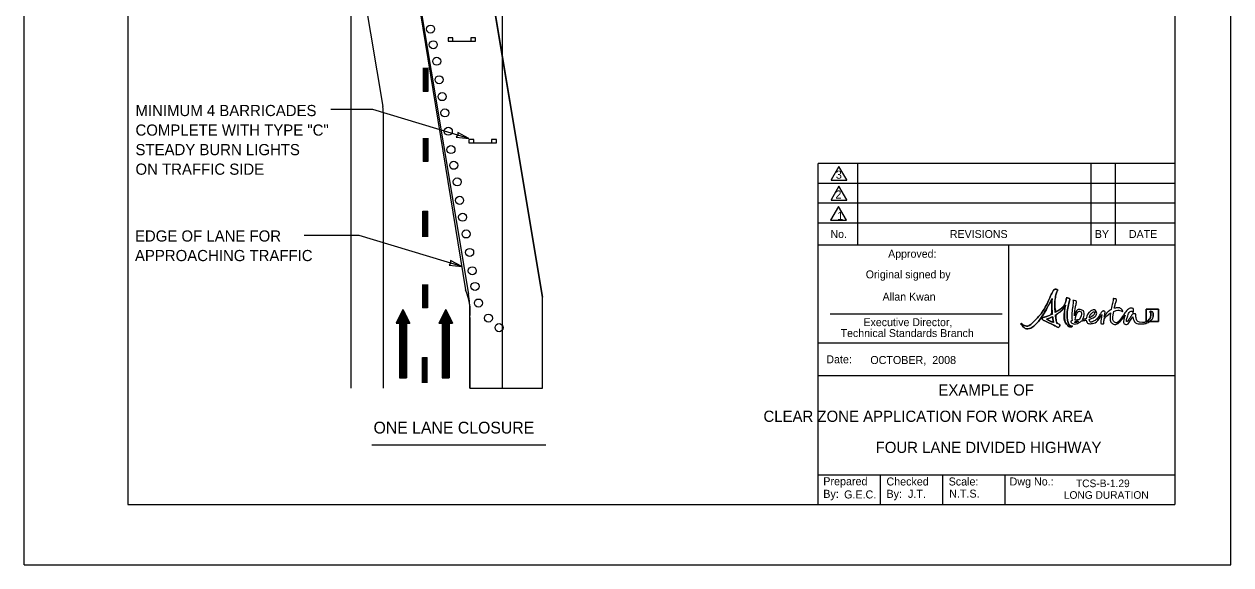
# Model space of a CAD drawing. Extents: x 3033 to 3249, y -403 to -124.
# Drawn here: x 3033.2 to 3249.2, y -402.6 to -305.8 of the extents above; entities that cross this region are included whole.
import ezdxf

# ---------------------------------------------------------------- set-up
doc = ezdxf.new("R2010")
doc.units = 0
for name, color, linetype in [('Level 1', 7, 'Continuous'), ('Level 10', 7, 'Continuous'), ('Level 17', 7, 'Continuous'), ('Level 22', 7, 'Continuous'), ('Level 36', 7, 'Continuous'), ('Level 44', 7, 'Continuous'), ('Level 5', 7, 'Continuous'), ('Level 53', 7, 'Continuous'), ('Level 60', 7, 'Continuous'), ('Level 7', 7, 'Continuous')]:
    doc.layers.add(name, color=color, linetype=linetype)

# ---------------------------------------------------------------- blocks, each defined once
blk = doc.blocks.new('arrow')
at = {"layer": 'Level 60'}
blk.add_lwpolyline([(0.6, 0.12), (0, 0), (0.6, -0.12), (0.56, 0)], close=True, dxfattribs=at)

msp = doc.modelspace()

# ---------------------------------------------------------------- linework, layer by layer
at = {"layer": 'Level 1'}
for p, q in [((3239.21, -334.32), (3175.36, -334.32)), ((3239.21, -337.87), (3175.36, -337.87)), ((3239.21, -341.41), (3175.36, -341.41)), ((3175.37, -391.78), (3175.37, -345.31)), ((3175.37, -345.31), (3239.21, -345.31)), ((3209.42, -345.31), (3209.42, -368.72)), ((3175.37, -362.87), (3209.42, -362.87)), ((3175.37, -368.72), (3239.21, -368.72)), ((3175.37, -386.46), (3239.21, -386.46)), ((3186.5, -391.78), (3186.5, -386.46)), ((3197.63, -391.78), (3197.63, -386.46)), ((3208.76, -386.46), (3208.76, -391.78))]:
    msp.add_line(p, q, dxfattribs=at)
msp.add_lwpolyline([(3178.99, -338.43), (3177.57, -340.9), (3180.41, -340.9)], close=True, dxfattribs=at)
at = {"layer": 'Level 10'}
for p, q in [((3118.83, -370.96), (3118.83, -242.11)), ((3091.73, -370.96), (3091.73, -261.76)), ((3101.51, -286.84), (3112.75, -354.13)), ((3092.01, -288.27), (3097.4, -320.57)), ((3101.92, -289.97), (3112.2, -353.34)), ((3097.54, -370.96), (3097.54, -322.22)), ((3101.02, -356.86), (3099.8, -359.31)), ((3100.26, -358.39), (3100.26, -359.31)), ((3100.41, -358.08), (3100.41, -369.13)), ((3100.56, -357.78), (3100.56, -369.13)), ((3100.71, -357.47), (3100.71, -369.13)), ((3100.87, -357.16), (3100.87, -369.13)), ((3101.02, -356.86), (3101.02, -369.13)), ((3101.02, -356.86), (3102.25, -359.31)), ((3101.18, -357.16), (3101.18, -369.13)), ((3101.33, -357.47), (3101.33, -369.13)), ((3101.48, -357.78), (3101.48, -369.13)), ((3101.64, -358.08), (3101.64, -369.13)), ((3101.79, -358.39), (3101.79, -359.31)), ((3108.68, -356.86), (3107.46, -359.31)), ((3107.92, -358.39), (3107.92, -359.31)), ((3108.07, -358.08), (3108.07, -369.13)), ((3108.22, -357.78), (3108.22, -369.13)), ((3108.37, -357.47), (3108.37, -369.13)), ((3108.53, -357.16), (3108.53, -369.13)), ((3108.68, -356.86), (3108.68, -369.13)), ((3108.68, -356.86), (3109.91, -359.31)), ((3108.84, -357.16), (3108.84, -369.13)), ((3108.99, -357.47), (3108.99, -369.13)), ((3109.14, -357.78), (3109.14, -369.13)), ((3109.3, -358.08), (3109.3, -369.13)), ((3109.45, -358.39), (3109.45, -359.31)), ((3113.02, -370.96), (3113.02, -357.42)), ((3099.8, -359.31), (3100.41, -359.31)), ((3099.95, -359), (3099.95, -359.31)), ((3100.1, -358.7), (3100.1, -359.31)), ((3100.41, -359.31), (3100.41, -369.13)), ((3101.64, -359.31), (3101.64, -369.13)), ((3101.64, -359.31), (3102.25, -359.31)), ((3101.94, -358.7), (3101.94, -359.31)), ((3102.1, -359), (3102.1, -359.31)), ((3107.46, -359.31), (3108.07, -359.31)), ((3107.61, -359), (3107.61, -359.31)), ((3107.76, -358.7), (3107.76, -359.31)), ((3108.07, -359.31), (3108.07, -369.13)), ((3109.3, -359.31), (3109.3, -369.13)), ((3109.3, -359.31), (3109.91, -359.31)), ((3109.6, -358.7), (3109.6, -359.31)), ((3109.76, -359), (3109.76, -359.31)), ((3100.41, -369.13), (3101.64, -369.13)), ((3108.07, -369.13), (3109.3, -369.13))]:
    msp.add_line(p, q, dxfattribs=at)
msp.add_lwpolyline([(3113.02, -358.31), (3113.02, -370.96), (3126.02, -370.96), (3126.02, -354.69), (3114.37, -284.95), (3114.35, -242.11), (3101.45, -242.09), (3101.37, -285.85), (3101.52, -287.39)], dxfattribs=at)
for centre in [(3105.96, -306.68), (3106.45, -309.49), (3107.07, -312.45), (3107.5, -315.75), (3108.04, -318.78), (3108.52, -321.68), (3109.14, -324.97), (3109.62, -328.26), (3110.11, -331.07), (3110.73, -334.03), (3111.16, -337.34), (3111.7, -340.36), (3112.33, -343.36), (3112.96, -346.66), (3113.43, -349.95), (3113.92, -352.75), (3114.54, -355.72), (3116.33, -358.42), (3118.22, -360.13)]:
    msp.add_circle(centre, 0.718, dxfattribs=at)
for centre, radius, start, end in [((3087.54, -322.22), 10, 0, 9.4843), ((3103.77, -357.29), 9.31, 353.6691, 25.0725), ((3093.02, -357.42), 20, 360, 9.4843)]:
    msp.add_arc(centre, radius, start, end, dxfattribs=at)
at = {"layer": 'Level 17'}
for p, q in [((3033.21, -402.59), (3033.21, -123.59)), ((3249.22, -402.59), (3249.22, -123.59)), ((3239.24, -330.76), (3175.36, -330.76)), ((3033.21, -402.59), (3249.22, -402.59))]:
    msp.add_line(p, q, dxfattribs=at)
at = {"layer": 'Level 22'}
for p, q in [((3051.75, -135.28), (3051.75, -391.78)), ((3239.21, -135.28), (3239.21, -391.78)), ((3051.75, -391.78), (3239.21, -391.78)), ((3190.83, -391.78), (3190.83, -391.78))]:
    msp.add_line(p, q, dxfattribs=at)
at = {"layer": 'Level 36'}
for p, q in [((3175.37, -337.24), (3175.37, -330.76)), ((3224.18, -330.76), (3224.18, -345.31)), ((3228.5, -330.76), (3228.5, -345.31))]:
    msp.add_line(p, q, dxfattribs=at)
at = {"layer": 'Level 44'}
for p, q in [((3105.49, -317.84), (3104.62, -317.84)), ((3105.49, -330.39), (3104.62, -330.39)), ((3104.59, -339.29), (3105.47, -339.29)), ((3105.4, -356.57), (3104.53, -356.57)), ((3104.51, -365.46), (3105.38, -365.46)), ((3095.43, -381.11), (3126.62, -381.11))]:
    msp.add_line(p, q, dxfattribs=at)
for points in [[(3104.62, -313.65), (3104.62, -317.84)], [(3104.77, -313.65), (3104.77, -317.84)], [(3104.91, -313.65), (3104.91, -317.84)], [(3105.06, -313.65), (3105.06, -317.84)], [(3105.2, -313.65), (3105.2, -317.84)], [(3105.35, -313.65), (3105.35, -317.84)], [(3105.49, -313.65), (3105.49, -317.84)], [(3104.62, -326.21), (3104.62, -330.39)], [(3104.77, -326.21), (3104.77, -330.39)], [(3104.91, -326.21), (3104.91, -330.39)], [(3105.06, -326.21), (3105.06, -330.39)], [(3105.2, -326.21), (3105.2, -330.39)], [(3105.35, -326.21), (3105.35, -330.39)], [(3105.49, -326.21), (3105.49, -330.39)], [(3104.59, -343.85), (3104.59, -339.29)], [(3104.74, -343.85), (3104.74, -339.29)], [(3104.89, -343.85), (3104.89, -339.29)], [(3105.03, -343.85), (3105.03, -339.29)], [(3105.18, -343.85), (3105.18, -339.29)], [(3105.32, -343.85), (3105.32, -339.29)], [(3105.47, -343.85), (3105.47, -339.29)], [(3104.53, -352.38), (3104.53, -356.57)], [(3104.68, -352.38), (3104.68, -356.57)], [(3104.82, -352.38), (3104.82, -356.57)], [(3104.97, -352.38), (3104.97, -356.57)], [(3105.11, -352.38), (3105.11, -356.57)], [(3105.26, -352.38), (3105.26, -356.57)], [(3105.4, -352.38), (3105.4, -356.57)], [(3104.51, -370.02), (3104.51, -365.46)], [(3104.65, -370.02), (3104.65, -365.46)], [(3104.8, -370.02), (3104.8, -365.46)], [(3104.94, -370.02), (3104.94, -365.46)], [(3105.09, -370.02), (3105.09, -365.46)], [(3105.23, -370.02), (3105.23, -365.46)], [(3105.38, -370.02), (3105.38, -365.46)]]:
    msp.add_lwpolyline(points, dxfattribs=at)
at = {"layer": 'Level 5'}
for p, q in [((3114.37, -284.95), (3126.02, -354.69)), ((3109.98, -308.23), (3109.11, -308.23)), ((3109.11, -308.23), (3109.11, -308.84)), ((3109.11, -308.84), (3114.03, -308.84)), ((3109.98, -308.84), (3109.98, -308.23)), ((3114.03, -308.23), (3113.16, -308.23)), ((3113.16, -308.23), (3113.16, -308.84)), ((3114.03, -308.84), (3114.03, -308.23)), ((3095.63, -321.05), (3088.12, -321.05)), ((3113.72, -326.45), (3112.84, -326.45)), ((3112.84, -326.45), (3112.84, -327.06)), ((3112.84, -327.06), (3117.77, -327.06)), ((3113.72, -327.06), (3113.72, -326.45)), ((3117.77, -326.45), (3116.9, -326.45)), ((3116.9, -326.45), (3116.9, -327.06)), ((3117.77, -327.06), (3117.77, -326.45)), ((3093.19, -343.64), (3083.32, -343.64)), ((3126.02, -370.96), (3126.02, -354.69))]:
    msp.add_line(p, q, dxfattribs=at)
for points in [[(3112.84, -326.25), (3095.63, -321.05)], [(3111.55, -349.19), (3093.19, -343.64)]]:
    msp.add_lwpolyline(points, dxfattribs=at)
at = {"layer": 'Level 53'}
msp.add_line((3234.65, -359.04), (3234.1, -359.04), dxfattribs=at)
msp.add_lwpolyline([(3234.65, -359.04), (3236.26, -359.04), (3236.26, -356.8), (3234.03, -356.8), (3234.03, -359.04), (3234.1, -359.04)], dxfattribs=at)
for points, degree in [([(3220.66, -359.84), (3220.42, -359.81), (3220.11, -359.48), (3220.01, -358.95), (3219.84, -357.98), (3219.94, -357.03), (3220.23, -355.6), (3220.28, -355.34), (3220.47, -354.87), (3219.88, -354.78), (3219.7, -354.75), (3219.79, -354.84), (3219.74, -355.09), (3219.52, -356.15), (3218.65, -356.91), (3217.78, -357.42), (3217.69, -356.21), (3217.73, -354.86), (3217.96, -354.04), (3218.15, -353.34), (3218.38, -353.47), (3218.09, -353.32), (3217.79, -353.17), (3217.47, -353.37), (3217.21, -353.89), (3216.95, -354.41), (3215.76, -357.23), (3213.85, -359.13), (3212.87, -360.1), (3211.98, -359.6), (3211.81, -359.45), (3211.66, -359.33), (3211.61, -359.52), (3211.79, -359.71), (3212.58, -360.56), (3213.73, -360.07), (3214.16, -359.65), (3215.32, -358.49), (3216.67, -355.99), (3217.22, -354.92), (3217.17, -355.52), (3217.15, -356.52), (3217.26, -357.7), (3216.67, -357.99), (3216.14, -358.16), (3215.89, -358.22), (3215.62, -358.29), (3215.45, -358.4), (3215.44, -358.53), (3215.44, -358.67), (3215.62, -358.78), (3215.88, -358.91), (3216.35, -359.13), (3217.72, -359.78), (3218.06, -359.98), (3218.35, -360.14), (3218.49, -360.01), (3218.58, -359.83), (3218.69, -359.6), (3218.38, -359.46), (3218.09, -359.37), (3217.97, -358.97), (3217.88, -358.44), (3217.82, -357.85), (3218.52, -357.42), (3219.2, -356.85), (3219.6, -356.13), (3219.5, -356.73), (3219.24, -358.76), (3219.88, -359.62), (3220.03, -359.81), (3220.34, -360.01), (3220.64, -359.98), (3220.79, -359.97), (3220.86, -359.87), (3220.84, -359.84), (3220.83, -359.82), (3220.75, -359.86), (3220.66, -359.84)], 3), ([(3217.78, -357.42), (3217.69, -356.21), (3217.73, -354.86), (3217.96, -354.04), (3218.15, -353.34), (3218.38, -353.47), (3218.09, -353.32), (3217.79, -353.17), (3217.47, -353.37), (3217.21, -353.89), (3216.95, -354.41), (3215.76, -357.23), (3213.85, -359.13), (3212.87, -360.1), (3211.98, -359.6), (3211.81, -359.45), (3211.66, -359.33), (3211.61, -359.52), (3211.79, -359.71), (3212.58, -360.56), (3213.73, -360.07), (3214.16, -359.65), (3215.32, -358.49), (3216.67, -355.99), (3217.22, -354.92)], 3), ([(3217.22, -354.92), (3217.17, -355.52), (3217.15, -356.52), (3217.26, -357.7)], 2), ([(3220.66, -359.84), (3220.42, -359.81), (3220.11, -359.48), (3220.01, -358.95), (3219.84, -357.98), (3219.94, -357.03), (3220.23, -355.6), (3220.28, -355.34), (3220.47, -354.87), (3219.88, -354.78), (3219.7, -354.75), (3219.79, -354.84), (3219.74, -355.09), (3219.52, -356.15), (3218.65, -356.91), (3217.78, -357.42)], 3), ([(3217.82, -357.85), (3218.52, -357.42), (3219.2, -356.85), (3219.6, -356.13)], 2), ([(3219.6, -356.13), (3219.5, -356.73), (3219.24, -358.76), (3219.88, -359.62), (3220.03, -359.81), (3220.34, -360.01), (3220.64, -359.98), (3220.79, -359.97), (3220.86, -359.87), (3220.84, -359.84), (3220.83, -359.82), (3220.75, -359.86), (3220.66, -359.84)], 3), ([(3221.2, -358), (3221.25, -357.43), (3221.34, -356.74), (3221.47, -356.1), (3221.52, -355.83), (3221.7, -355.36), (3221.12, -355.27), (3220.93, -355.25), (3220.96, -355.33), (3220.98, -355.58), (3221, -355.92), (3220.63, -357.96), (3220.82, -358.86)], 3), ([(3228.35, -356.66), (3228.42, -356.36), (3228.49, -356.06), (3228.58, -355.77), (3228.65, -355.5), (3228.87, -355.03), (3228.3, -354.94), (3228.11, -354.92), (3228.19, -355), (3228.13, -355.25), (3228.02, -355.71), (3227.88, -356.3), (3227.78, -356.9)], 3), ([(3217.26, -357.7), (3216.67, -357.99), (3216.14, -358.16), (3215.89, -358.22), (3215.62, -358.29), (3215.45, -358.4), (3215.44, -358.53), (3215.44, -358.67), (3215.62, -358.78), (3215.88, -358.91), (3216.35, -359.13), (3217.72, -359.78), (3218.06, -359.98), (3218.35, -360.14), (3218.49, -360.01), (3218.58, -359.83), (3218.69, -359.6), (3218.38, -359.46), (3218.09, -359.37)], 3), ([(3216.19, -358.63), (3216.5, -358.52), (3216.89, -358.35), (3217.31, -358.14)], 2), ([(3216.19, -358.63), (3216.5, -358.52), (3216.89, -358.35), (3217.31, -358.14), (3217.36, -358.61), (3217.42, -358.95), (3217.49, -359.21), (3217.19, -359.1), (3216.76, -358.92), (3216.19, -358.63)], 3), ([(3217.31, -358.14), (3217.36, -358.61), (3217.42, -358.95), (3217.49, -359.21)], 2), ([(3218.09, -359.37), (3217.97, -358.97), (3217.88, -358.44), (3217.82, -357.85)], 2), ([(3222.64, -358.66), (3223.05, -357.99), (3223.02, -357.08), (3222.41, -356.93), (3221.71, -356.75), (3221.35, -357.43), (3221.2, -358)], 3), ([(3221.35, -358.79), (3221.44, -358.08), (3221.82, -357.08), (3222.28, -357.24), (3222.55, -357.33), (3222.41, -358.17), (3222.07, -358.73)], 3), ([(3223.34, -358.55), (3223.13, -358.59), (3222.9, -358.63), (3222.64, -358.66)], 2), ([(3223.86, -358.64), (3223.96, -358.61), (3224.05, -358.58), (3224.12, -358.55), (3225, -358.16), (3225.31, -357.57), (3225.08, -357.21), (3224.87, -356.87), (3224.26, -356.97), (3223.78, -357.48), (3223.54, -357.73), (3223.36, -358.16), (3223.34, -358.55)], 3), ([(3223.34, -358.77), (3223.39, -359.16), (3223.65, -359.46), (3224.24, -359.41), (3225.09, -359.33), (3225.84, -358.29), (3226.13, -357.79)], 3), ([(3226.54, -358.23), (3226.59, -357.95), (3226.68, -357.64), (3226.69, -357.44), (3226.69, -357.22), (3226.54, -357.17), (3226.49, -357.16), (3226.36, -357.12), (3226.21, -357.18), (3226.06, -357.4), (3225.7, -357.89), (3225.26, -358.68), (3224.58, -359.01), (3224.09, -359.25), (3223.88, -359.01), (3223.86, -358.64)], 3), ([(3224.34, -357.52), (3224.63, -357.25), (3224.78, -357.27), (3224.82, -357.34), (3224.9, -357.5), (3224.55, -358.06), (3223.89, -358.37)], 3), ([(3223.89, -358.37), (3223.94, -358.07), (3224.1, -357.74), (3224.34, -357.52)], 2), ([(3226.13, -357.79), (3226.07, -358.32), (3225.73, -359.5), (3226.32, -359.44), (3226.55, -359.41), (3226.45, -359.37), (3226.47, -359.17), (3226.52, -358.47), (3227.11, -357.87), (3227.69, -357.5)], 3), ([(3227.78, -356.9), (3227.3, -357.17), (3226.86, -357.63), (3226.54, -358.23)], 2), ([(3227.69, -357.5), (3227.59, -358.37), (3227.62, -359.14), (3228.02, -359.38), (3228.74, -359.83), (3229.76, -358.65), (3230.32, -357.92)], 3), ([(3233.41, -359.23), (3232.49, -359.23), (3232.26, -358.52), (3232.21, -358.17), (3232.18, -357.94), (3232.23, -357.6), (3231.83, -357.64), (3231.55, -357.67), (3231.29, -358.22), (3230.93, -358.69), (3230.62, -359.09), (3230.49, -359.05), (3230.56, -358.71), (3230.65, -358.28), (3231, -357.27), (3231.41, -357.2), (3231.6, -357.17), (3231.67, -357.5), (3231.76, -357.29), (3231.84, -357.08), (3231.76, -356.63), (3231.34, -356.63), (3231.04, -356.63), (3230.69, -356.95), (3230.4, -357.3), (3230.14, -357.62), (3228.86, -359.51), (3228.32, -359.1), (3228.07, -358.91), (3228.09, -358.13), (3228.25, -357.22)], 3), ([(3228.25, -357.22), (3228.89, -356.97), (3229.42, -357.05), (3229.72, -357.19), (3229.87, -357.27), (3229.89, -357.25), (3229.82, -357.09), (3229.73, -356.85), (3229.22, -356.48), (3228.41, -356.65), (3228.39, -356.65), (3228.37, -356.66), (3228.35, -356.66)], 3), ([(3230.32, -357.92), (3230.04, -358.56), (3229.87, -359.39), (3230.3, -359.52), (3230.81, -359.67), (3231.21, -358.83), (3231.67, -358.19)], 3), ([(3231.67, -358.19), (3231.73, -358.65), (3232.03, -359.44), (3233.27, -359.44), (3233.83, -359.44), (3234.3, -359.28), (3234.65, -359.04)], 3), ([(3234.03, -356.8), (3234.03, -356.8), (3234.03, -359.04), (3234.03, -359.04), (3234.03, -359.04), (3234.1, -359.04), (3234.1, -359.04), (3234.58, -358.75), (3234.91, -358.19), (3234.91, -357.73), (3234.91, -357.34), (3234.7, -357.36), (3234.72, -357.31), (3234.79, -357.15), (3235.28, -357.24), (3235.31, -357.79), (3235.34, -358.27), (3235.09, -358.72), (3234.65, -359.04), (3234.65, -359.04), (3236.26, -359.04), (3236.26, -359.04), (3236.26, -359.04), (3236.26, -356.8), (3236.26, -356.8), (3236.26, -356.8), (3234.03, -356.8), (3234.03, -356.8)], 3), ([(3234.1, -359.04), (3234.58, -358.75), (3234.91, -358.19), (3234.91, -357.73), (3234.91, -357.34), (3234.7, -357.36), (3234.72, -357.31), (3234.79, -357.15), (3235.28, -357.24), (3235.31, -357.79), (3235.34, -358.27), (3235.09, -358.72), (3234.65, -359.04)], 3), ([(3217.49, -359.21), (3217.19, -359.1), (3216.76, -358.92), (3216.19, -358.63)], 2), ([(3220.82, -358.86), (3220.57, -358.94), (3220.47, -359.13), (3220.79, -359.32), (3221.01, -359.46), (3221.5, -359.51), (3222, -359.26), (3222.18, -359.18), (3222.33, -359.05), (3222.46, -358.91)], 3), ([(3221.28, -359.23), (3221.31, -359.2), (3221.33, -359.16), (3221.33, -359.11), (3221.33, -359.08), (3221.33, -359.05), (3221.33, -359.01)], 3), ([(3221.48, -359.22), (3221.4, -359.24), (3221.33, -359.24), (3221.28, -359.23)], 2), ([(3221.33, -359.01), (3221.46, -359.01), (3221.65, -358.99), (3221.89, -358.97)], 2), ([(3222.07, -358.73), (3221.84, -358.75), (3221.6, -358.77), (3221.35, -358.79)], 2), ([(3221.89, -358.97), (3221.76, -359.11), (3221.63, -359.2), (3221.48, -359.22)], 2), ([(3222.46, -358.91), (3222.75, -358.87), (3223.06, -358.82), (3223.34, -358.77)], 2), ([(3234.1, -359.04), (3233.89, -359.16), (3233.66, -359.23), (3233.41, -359.23)], 2)]:
    msp.add_open_spline(points, degree=degree, dxfattribs=at)
at = {"layer": 'Level 60'}
for p, q in [((3182.46, -345.31), (3182.46, -330.76)), ((3175.37, -337.24), (3175.37, -334.32)), ((3175.37, -345.31), (3175.37, -337.24)), ((3211.59, -359.47), (3211.72, -359.47))]:
    msp.add_line(p, q, dxfattribs=at)
for points in [[(3179.07, -331.27), (3177.68, -333.69)], [(3180.46, -333.69), (3179.07, -331.27)], [(3177.68, -333.69), (3177.65, -333.74), (3180.49, -333.74), (3180.46, -333.69)], [(3179.07, -334.82), (3177.68, -337.24)], [(3180.46, -337.24), (3179.07, -334.82)], [(3177.68, -337.24), (3177.65, -337.29), (3180.49, -337.29), (3180.46, -337.24)]]:
    msp.add_lwpolyline(points, dxfattribs=at)
at = {"layer": 'Level 7'}
msp.add_line((3177.48, -357.63), (3208.28, -357.63), dxfattribs=at)

# ---------------------------------------------------------------- block references
at = {"layer": 'Level 5', "xscale": 3.75, "yscale": 3.7500000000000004, "rotation": 163.1852984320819}
for p in [(3112.84, -326.25), (3111.55, -349.19)]:
    msp.add_blockref('arrow', p, dxfattribs=at)

# ---------------------------------------------------------------- texts
at = {"layer": 'Level 1'}
for s, height, p in [('3', 1.45, (3178.5, -333.47)), ('2', 1.45, (3178.44, -337.02)), ('1', 1.45, (3178.76, -340.84)), ('No.', 1.419, (3177.54, -344.08)), ('REVISIONS', 1.419, (3198.92, -344.08)), ('Date:', 1.433, (3176.8, -366.51)), ('Prepared', 1.44, (3176.26, -388.34)), ('Checked', 1.433, (3187.57, -388.38)), ('Scale:', 1.433, (3198.7, -388.38)), ('Dwg No.:', 1.433, (3209.61, -388.38)), ('By:', 1.44, (3176.26, -390.59)), ('By:  J.T.', 1.44, (3187.57, -390.59)), ('    N.T.S.   ', 1.4329, (3196.67, -390.55))]:
    msp.add_text(s, height=height, rotation=360, dxfattribs=at).set_placement(p)
msp.add_text('G.E.C.', height=1.433, dxfattribs=at).set_placement((3179.99, -390.7))
at = {"layer": 'Level 17'}
for s, p in [('BY', (3224.87, -344.08)), ('DATE', (3230.97, -344.08))]:
    msp.add_text(s, height=1.419, rotation=360, dxfattribs=at).set_placement(p)
at = {"layer": 'Level 44'}
for s, height, p in [('EXAMPLE OF', 2, (3196.87, -372.28)), ('        CLEAR ZONE APPLICATION FOR WORK AREA', 2, (3159.61, -376.99)), ('ONE LANE CLOSURE', 2.1152, (3095.76, -379.08)), ('FOUR LANE DIVIDED HIGHWAY', 2, (3185.63, -382.56))]:
    msp.add_text(s, height=height, dxfattribs=at).set_placement(p)
at = {"layer": 'Level 5'}
for s, p in [('MINIMUM 4 BARRICADES', (3053.15, -322.26)), ('COMPLETE WITH TYPE "C" ', (3053.15, -325.76)), ('STEADY BURN LIGHTS', (3053.15, -329.26)), ('ON TRAFFIC SIDE', (3053.15, -332.76)), ('EDGE OF LANE FOR', (3053.05, -344.72)), ('APPROACHING TRAFFIC', (3053.05, -348.22))]:
    msp.add_text(s, height=2, dxfattribs=at).set_placement(p)
at = {"layer": 'Level 60'}
for s, height, p in [('OCTOBER,  2008', 1.434, (3184.68, -366.64)), ('TCS-B-1.29', 1.362, (3221.49, -388.68)), ('LONG DURATION', 1.3624, (3219.32, -390.76))]:
    msp.add_text(s, height=height, dxfattribs=at).set_placement(p)
at = {"layer": 'Level 7'}
for s, height, p in [('Approved:', 1.419, (3187.87, -347.61)), ('Approved:', 1.419, (3187.87, -347.61)), ('Approved:', 1.419, (3187.87, -347.61)), ('Original signed by', 1.4187, (3183.86, -351.3)), ('Allan Kwan', 1.419, (3186.87, -355.29)), ('Executive Director,', 1.4187, (3183.45, -359.86)), ('Technical Standards Branch', 1.4187, (3179.36, -361.81))]:
    msp.add_text(s, height=height, dxfattribs=at).set_placement(p)

doc.saveas('drawing.dxf')
